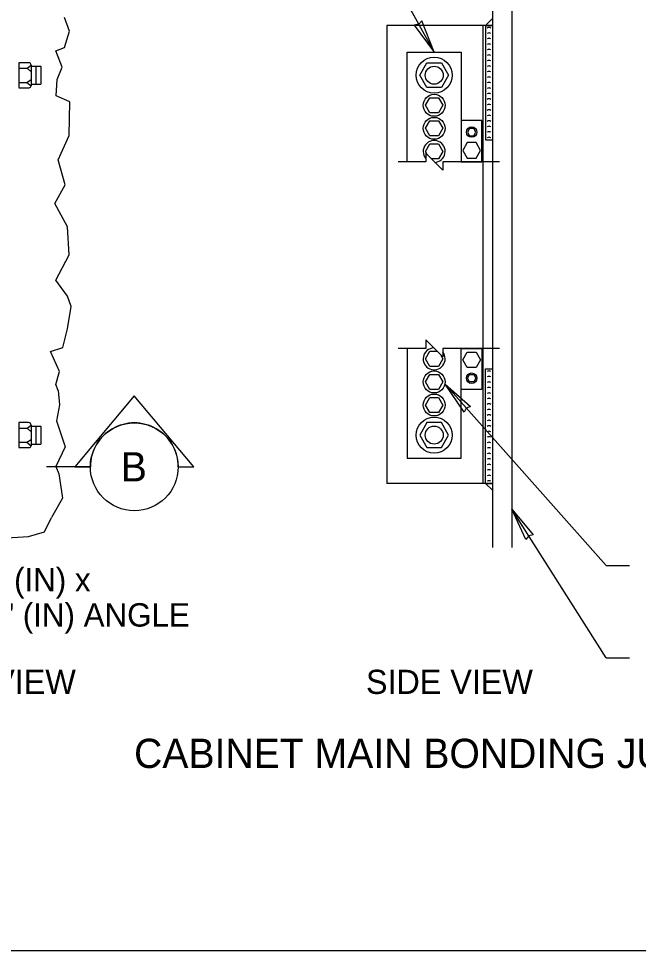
# Model space of a CAD drawing. Extents: x 99862 to 103680, y 99470 to 105076.
# Drawn here: x 100392 to 100816, y 103000 to 103636 of the extents above; entities that cross this region are included whole.
import ezdxf

# ---------------------------------------------------------------- set-up
doc = ezdxf.new("R2010")
doc.units = 0
for name, color, linetype in [('Level 1', 7, 'Continuous'), ('Level 11', 7, 'Continuous'), ('Level 15', 7, 'Continuous'), ('Level 20', 7, 'Continuous'), ('Level 40', 7, 'Continuous')]:
    doc.layers.add(name, color=color, linetype=linetype)

msp = doc.modelspace()

# ---------------------------------------------------------------- linework, layer by layer
at = {"layer": 'Level 1'}
for p, q in [((100711.15, 103631.31), (100715.82, 103635.99)), ((100711.15, 103631.31), (100715.82, 103631.31)), ((100711.15, 103631.31), (100711.15, 103553.11)), ((100392.23, 103605.9), (100392.23, 103588.83)), ((100392.23, 103602.06), (100397.94, 103602.06)), ((100397.94, 103602.06), (100400.56, 103604.1)), ((100397.94, 103602.06), (100400.56, 103599.59)), ((100400.56, 103604.1), (100400.56, 103590.13)), ((100397.73, 103592.44), (100400.56, 103594.44)), ((100392.23, 103592.44), (100397.73, 103592.44)), ((100392.23, 103588.82), (100399.24, 103588.82)), ((100397.73, 103592.44), (100400.56, 103590.13)), ((100708.67, 103566.3), (100694.54, 103566.3)), ((100708.67, 103538.18), (100708.67, 103566.3)), ((100711.15, 103553.11), (100715.82, 103553.11)), ((100694.54, 103538.18), (100708.67, 103538.18)), ((100694.54, 103410.66), (100708.67, 103410.66)), ((100708.67, 103410.66), (100708.67, 103382.54)), ((100711.15, 103396.72), (100715.82, 103396.72)), ((100711.15, 103318.52), (100711.15, 103396.72)), ((100708.67, 103382.54), (100694.54, 103382.54)), ((100392.23, 103360.01), (100392.23, 103342.94)), ((100392.23, 103356.17), (100397.94, 103356.17)), ((100397.94, 103356.17), (100400.56, 103358.22)), ((100397.94, 103356.17), (100400.56, 103353.7)), ((100400.56, 103358.22), (100400.56, 103344.24)), ((100392.23, 103346.56), (100397.73, 103346.56)), ((100397.73, 103346.56), (100400.56, 103348.55)), ((100397.73, 103346.56), (100400.56, 103344.24)), ((100392.23, 103342.94), (100399.24, 103342.94)), ((100711.15, 103318.52), (100715.82, 103318.52)), ((100715.82, 103313.84), (100711.15, 103318.52))]:
    msp.add_line(p, q, dxfattribs=at)
for points in [[(99862, 102999.5), (103151, 102999.5), (103151, 105075.5), (99862, 105075.5)], [(100698.68, 103558.48), (100700.15, 103555.95), (100703.07, 103555.95), (100704.53, 103558.48), (100703.07, 103561.01), (100700.15, 103561.01)], [(100695.52, 103545.99), (100698.56, 103540.72), (100704.65, 103540.72), (100707.69, 103545.99), (100704.65, 103551.26), (100698.56, 103551.26)], [(100695.52, 103402.85), (100698.56, 103408.12), (100704.65, 103408.12), (100707.69, 103402.85), (100704.65, 103397.58), (100698.56, 103397.58)], [(100698.68, 103390.36), (100700.15, 103392.89), (100703.07, 103392.89), (100704.53, 103390.36), (100703.07, 103387.83), (100700.15, 103387.83)]]:
    msp.add_lwpolyline(points, close=True, dxfattribs=at)
for centre in [(100701.61, 103558.48), (100701.61, 103390.36)]:
    msp.add_circle(centre, 3.58, dxfattribs=at)
for centre, radius, start, end in [((100713.48, 103627.68), 2.25, 57.42233, 122.57775), ((100713.48, 103623.93), 2.25, 57.42233, 122.57775), ((100713.48, 103620.18), 2.25, 57.42233, 122.57775), ((100713.48, 103616.43), 2.25, 57.42233, 122.57775), ((100713.48, 103612.68), 2.25, 57.42233, 122.57775), ((100713.48, 103608.93), 2.25, 57.42233, 122.57775), ((100713.48, 103605.18), 2.25, 57.42233, 122.57775), ((100398.82, 103604.15), 1.75, 358.62534, 88.62534), ((100713.48, 103601.43), 2.25, 57.42233, 122.57775), ((100713.48, 103597.68), 2.25, 57.42233, 122.57775), ((100713.48, 103593.93), 2.25, 57.42233, 122.57775), ((100399.25, 103590.13), 1.31, 270, 0), ((100713.48, 103590.18), 2.25, 57.42233, 122.57775), ((100713.48, 103586.43), 2.25, 57.42233, 122.57775), ((100713.48, 103582.68), 2.25, 57.42233, 122.57775), ((100713.48, 103578.93), 2.25, 57.42233, 122.57775), ((100713.48, 103575.18), 2.25, 57.42233, 122.57775), ((100713.48, 103571.43), 2.25, 57.42233, 122.57775), ((100713.48, 103567.68), 2.25, 57.42233, 122.57775), ((100713.48, 103563.93), 2.25, 57.42233, 122.57775), ((100713.48, 103560.18), 2.25, 57.42233, 122.57775), ((100713.48, 103556.43), 2.25, 57.42233, 122.57775), ((100713.48, 103552.68), 2.25, 57.42233, 122.57775), ((100713.48, 103393.08), 2.25, 57.42233, 122.57775), ((100713.48, 103389.33), 2.25, 57.42233, 122.57775), ((100713.48, 103385.58), 2.25, 57.42233, 122.57775), ((100713.48, 103381.83), 2.25, 57.42233, 122.57775), ((100713.48, 103378.08), 2.25, 57.42233, 122.57775), ((100713.48, 103374.33), 2.25, 57.42233, 122.57775), ((100713.48, 103370.58), 2.25, 57.42233, 122.57775), ((100713.48, 103366.83), 2.25, 57.42233, 122.57775), ((100713.48, 103363.08), 2.25, 57.42233, 122.57775), ((100398.82, 103358.26), 1.75, 358.62534, 88.62534), ((100713.48, 103359.33), 2.25, 57.42233, 122.57775), ((100713.48, 103355.58), 2.25, 57.42233, 122.57775), ((100713.48, 103351.83), 2.25, 57.42233, 122.57775), ((100713.48, 103348.08), 2.25, 57.42233, 122.57775), ((100713.48, 103344.33), 2.25, 57.42233, 122.57775), ((100399.25, 103344.24), 1.31, 270, 0), ((100713.48, 103340.58), 2.25, 57.42233, 122.57775), ((100713.48, 103336.83), 2.25, 57.42233, 122.57775), ((100713.48, 103333.08), 2.25, 57.42233, 122.57775), ((100713.48, 103329.33), 2.25, 57.42233, 122.57775), ((100713.48, 103325.58), 2.25, 57.42233, 122.57775), ((100713.48, 103321.83), 2.25, 57.42233, 122.57775), ((100713.48, 103318.08), 2.25, 57.42233, 122.57775)]:
    msp.add_arc(centre, radius, start, end, dxfattribs=at)
at = {"layer": 'Level 11'}
for points in [[(100670.2, 103538.18), (100657.46, 103538.18), (100657.46, 103613.09), (100694.54, 103613.09), (100694.54, 103538.18), (100681.81, 103538.18)], [(100670.2, 103410.66), (100657.46, 103410.66), (100657.46, 103335.75), (100694.54, 103335.75), (100694.54, 103410.66), (100681.81, 103410.66)]]:
    msp.add_lwpolyline(points, dxfattribs=at)
at = {"layer": 'Level 15'}
for p, q in [((100644.96, 103669.27), (100676, 103613.09)), ((100793.51, 103262.47), (100683.5, 103386.19)), ((100793.51, 103199.33), (100728.96, 103300.96)), ((100793.51, 103262.47), (100809.51, 103262.47)), ((100793.51, 103199.33), (100809.51, 103199.33))]:
    msp.add_line(p, q, dxfattribs=at)
for points in [[(100676, 103613.09), (100667.58, 103634.51), (100665.47, 103632.14), (100662.35, 103631.62)], [(100683.5, 103386.19), (100700.88, 103371.09), (100697.95, 103369.9), (100696.41, 103367.13)], [(100728.96, 103300.96), (100743.72, 103283.29), (100740.63, 103282.58), (100738.68, 103280.09)]]:
    msp.add_lwpolyline(points, close=True, dxfattribs=at)
for points in [[(100720.67, 103538.18), (100681.81, 103538.18), (100681.81, 103532.37), (100670.2, 103543.99), (100670.2, 103538.18), (100651.38, 103538.18)], [(100720.67, 103410.66), (100681.81, 103410.66), (100681.81, 103404.85), (100670.2, 103416.47), (100670.2, 103410.66), (100651.38, 103410.66)]]:
    msp.add_lwpolyline(points, dxfattribs=at)
at = {"layer": 'Level 20'}
for p, q in [((100471.11, 103378.28), (100430.5, 103329.81)), ((100511.71, 103329.81), (100471.11, 103378.28)), ((100441.11, 103329.82), (100411.11, 103329.82)), ((100430.5, 103329.81), (100441.11, 103329.81)), ((100501.11, 103329.81), (100511.71, 103329.81))]:
    msp.add_line(p, q, dxfattribs=at)
msp.add_circle((100471.11, 103329.82), 30, dxfattribs=at)
msp.add_arc((100471.11, 103329.82), 30, 359.99779, 180.00221, dxfattribs=at)
at = {"layer": 'Level 40'}
for p, q in [((100715.82, 103700.17), (100715.82, 103274.68)), ((100728.96, 103700.17), (100728.96, 103274.68)), ((100643.56, 103631.31), (100643.56, 103318.52)), ((100715.82, 103631.31), (100643.56, 103631.31)), ((100709.25, 103631.31), (100709.25, 103318.52)), ((100715.82, 103631.31), (100715.82, 103318.52)), ((100398.86, 103605.89), (100392.23, 103605.89)), ((100400.56, 103603.52), (100407.34, 103603.52)), ((100403.83, 103603.52), (100403.83, 103591.2)), ((100407.34, 103603.52), (100407.34, 103591.2)), ((100666.15, 103597.36), (100671.08, 103605.9)), ((100671.08, 103605.9), (100680.93, 103605.9)), ((100680.93, 103605.9), (100685.86, 103597.36)), ((100671.08, 103588.83), (100666.15, 103597.36)), ((100685.86, 103597.36), (100680.93, 103588.83)), ((100400.56, 103591.2), (100407.34, 103591.2)), ((100680.93, 103588.83), (100671.08, 103588.83)), ((100670, 103576.8), (100673, 103581.99)), ((100673, 103581.99), (100679, 103581.99)), ((100679, 103581.99), (100682, 103576.8)), ((100673, 103571.6), (100670, 103576.8)), ((100682, 103576.8), (100679, 103571.6)), ((100679, 103571.6), (100673, 103571.6)), ((100670, 103561.05), (100673, 103566.24)), ((100673, 103566.24), (100679, 103566.24)), ((100679, 103566.24), (100682, 103561.05)), ((100673, 103555.85), (100670, 103561.05)), ((100682, 103561.05), (100679, 103555.85)), ((100670, 103545.3), (100673, 103550.49)), ((100679, 103555.85), (100673, 103555.85)), ((100673, 103550.49), (100679, 103550.49)), ((100679, 103550.49), (100682, 103545.3)), ((100671.53, 103542.66), (100670, 103545.3)), ((100682, 103545.3), (100679, 103540.1)), ((100679, 103540.1), (100674.09, 103540.1)), ((100670, 103403.55), (100673, 103408.74)), ((100673, 103398.35), (100670, 103403.55)), ((100673, 103408.74), (100677.92, 103408.74)), ((100682, 103403.55), (100679, 103398.35)), ((100680.48, 103406.18), (100682, 103403.55)), ((100679, 103398.35), (100673, 103398.35)), ((100670, 103387.8), (100673, 103392.99)), ((100673, 103392.99), (100679, 103392.99)), ((100679, 103392.99), (100682, 103387.8)), ((100673, 103382.6), (100670, 103387.8)), ((100682, 103387.8), (100679, 103382.6)), ((100679, 103382.6), (100673, 103382.6)), ((100670, 103372.05), (100673, 103377.24)), ((100673, 103366.85), (100670, 103372.05)), ((100673, 103377.24), (100679, 103377.24)), ((100679, 103377.24), (100682, 103372.05)), ((100682, 103372.05), (100679, 103366.85)), ((100679, 103366.85), (100673, 103366.85)), ((100398.86, 103360.01), (100392.23, 103360.01)), ((100671.08, 103360.01), (100666.15, 103351.48)), ((100680.93, 103360.01), (100671.08, 103360.01)), ((100685.86, 103351.48), (100680.93, 103360.01)), ((100400.56, 103357.64), (100407.34, 103357.64)), ((100403.83, 103357.64), (100403.83, 103345.32)), ((100407.34, 103357.64), (100407.34, 103345.32)), ((100666.15, 103351.48), (100671.08, 103342.94)), ((100680.93, 103342.94), (100685.86, 103351.48)), ((100400.56, 103345.32), (100407.34, 103345.32)), ((100671.08, 103342.94), (100680.93, 103342.94)), ((100715.82, 103318.52), (100643.56, 103318.52))]:
    msp.add_line(p, q, dxfattribs=at)
for points in [[(100419.09, 103381.99), (100417.55, 103386.09), (100420.04, 103394.89), (100413.93, 103408.53), (100422.23, 103411.33), (100425.45, 103424.07), (100427.98, 103439.45), (100425.52, 103446.4), (100417.55, 103457.29), (100426.57, 103474.58), (100425.45, 103493.68), (100416.74, 103509.71), (100423.77, 103522.36), (100419.13, 103539.56), (100426.57, 103556.09), (100427.03, 103579.12), (100417.68, 103583.26), (100418.38, 103594.5), (100421.89, 103602.93), (100417.55, 103613.92), (100423.3, 103616.29), (100426.81, 103627.53), (100423.3, 103636.66)], [(100419.09, 103381.99), (100420.01, 103372.06), (100417.86, 103361.14), (100423.97, 103343.55), (100417.44, 103329.97), (100419.63, 103324.99), (100422.1, 103308.49), (100414.61, 103295.13)], [(100220.3, 103288.45), (100230.26, 103288.45), (100240.94, 103285.3), (100259.03, 103289.76), (100271.94, 103282.01), (100277.11, 103283.73), (100292.6, 103282.01), (100306.37, 103275.98), (100322.73, 103277.7), (100335.64, 103284.59), (100346.83, 103284.59), (100356.3, 103277.7), (100370.94, 103275.98), (100380.41, 103281.15), (100398.78, 103282.26), (100409.78, 103285.41), (100414.61, 103295.13)]]:
    msp.add_lwpolyline(points, dxfattribs=at)
for centre, radius in [((100676, 103597.36), 12.32), ((100676, 103597.36), 6.16), ((100676, 103576.8), 7.5), ((100676, 103561.05), 7.5), ((100676, 103387.8), 7.5), ((100676, 103372.05), 7.5), ((100676, 103351.48), 12.32), ((100676, 103351.48), 6.16)]:
    msp.add_circle(centre, radius, dxfattribs=at)
for centre, start, end in [((100676, 103545.3), 272.87528, 219.25897), ((100676, 103403.55), 92.87531, 39.25899)]:
    msp.add_arc(centre, 7.5, start, end, dxfattribs=at)

# ---------------------------------------------------------------- texts
at = {"layer": 'Level 20'}
for s, height, p in [('B', 20, (100461.86, 103319.82)), ('3/16" (IN) x 2" (IN) x ', 16, (100250.11, 103244.67)), ('2" (IN) x 7 5/8" (IN) ANGLE', 16, (100250.11, 103220.67)), ('ELEVATION VIEW', 16.5, (100244.77, 103174.68)), ('SIDE VIEW', 16.5, (100629.41, 103174.68)), ('CABINET MAIN BONDING JUMPER ASSEMBLY DETAIL', 20, (100470.95, 103124.08))]:
    msp.add_text(s, height=height, dxfattribs=at).set_placement(p)

doc.saveas('drawing.dxf')
